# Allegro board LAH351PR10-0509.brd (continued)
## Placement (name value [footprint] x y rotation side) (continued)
CG887  0.47U_0201_4V_M  [C_0201]  33.32 62.21 90 bottom
CG888  4.7U_0402_4V_M  [C_0402]  34.09 62.21 90 bottom
CG889  0.47U_0201_4V_M  [C_0201]  35.31 62.21 90 bottom
CG895  20P_0402_50V8  [C_0402]  68.69 95.79 0 top
CG896  1U_0201_4V6M  [C_0201]  54.25 88.8 0 bottom
CG907  1U_0201_4V6M  [C_0201]  54.25 88.23 0 bottom
CG908  1U_0201_4V6M  [C_0201]  40.61 90.24 90 bottom
CG909  1U_0201_4V6M  [C_0201]  34.25 111.22 0 bottom
CG910  1U_0201_4V6M  [C_0201]  51.37 99.63 270 bottom
CG911  4.7U_0402_4V_M  [C_0402]  52.68 87.5 90 bottom
CG6501  22U_0603_4V_M  [C_0603]  53.91 87.34 0 bottom
CG6502  1U_0201_4V6M  [C_0201]  52.55 96.55 180 bottom
CG6506  4.7U_0402_4V_M  [C_0402]  56.52 113.36 90 bottom
CG6507  22U_0603_4V_M  [C_0603]  57.4 94.2 90 bottom
CG6508  1U_0201_4V6M  [C_0201]  58.55 113.53 90 bottom
CG6509  1U_0201_4V6M  [C_0201]  53.59 94.41 90 bottom
CG6522  0.47U_0201_4V_M  [C_0201]  39.05 127.94 90 bottom
CG6523  0.47U_0201_4V_M  [C_0201]  40.01 128.01 90 bottom
CG6524  0.47U_0201_4V_M  [C_0201]  36.6 128.93 0 bottom
CG6525  0.47U_0201_4V_M  [C_0201]  35.61 133.05 90 bottom
CG6526  0.47U_0201_4V_M  [C_0201]  35 136.98 0 bottom
CG6527  0.47U_0201_4V_M  [C_0201]  39.47 125.88 180 bottom
CG6528  0.47U_0201_4V_M  [C_0201]  42.51 134.99 270 top
CG6529  0.47U_0201_4V_M  [C_0201]  42.51 136.19 270 top
CG6530  0.47U_0201_4V_M  [C_0201]  42.51 137.4 270 top
CG6531  0.47U_0201_4V_M  [C_0201]  35.54 135.51 180 bottom
CG6532  0.47U_0201_4V_M  [C_0201]  38.6 137.26 90 bottom
CG6533  0.47U_0201_4V_M  [C_0201]  40.4 133.69 90 bottom
CG6534  0.47U_0201_4V_M  [C_0201]  38.73 136.03 180 bottom
CG6535  0.47U_0201_4V_M  [C_0201]  35.04 133.05 90 bottom
CG6536  0.47U_0201_4V_M  [C_0201]  30.23 127.83 270 bottom
CG6537  0.47U_0201_4V_M  [C_0201]  36.26 136.99 0 bottom
CG6538  0.47U_0201_4V_M  [C_0201]  32.09 128.3 0 bottom
CG6539  0.47U_0201_4V_M  [C_0201]  40.4 133.05 270 bottom
CG6540  0.47U_0201_4V_M  [C_0201]  40.01 126.48 90 bottom
CG6541  0.47U_0201_4V_M  [C_0201]  26.86 137.91 270 top
CG6542  0.47U_0201_4V_M  [C_0201]  35.53 136.18 180 bottom
CG6543  0.47U_0201_4V_M  [C_0201]  28.45 127.49 90 bottom
CG6544  0.47U_0201_4V_M  [C_0201]  33.6 126.77 90 bottom
CG6545  0.47U_0201_4V_M  [C_0201]  30.23 129.47 90 bottom
CG6546  0.47U_0201_4V_M  [C_0201]  37.45 137.14 270 bottom
CG6547  0.47U_0201_4V_M  [C_0201]  29.74 125.95 0 bottom
CG6548  0.47U_0201_4V_M  [C_0201]  37.34 134.88 270 bottom
CG6549  0.47U_0201_4V_M  [C_0201]  36.35 135.73 0 bottom
CG6550  0.47U_0201_4V_M  [C_0201]  29.02 127.49 90 bottom
CG6551  0.47U_0201_4V_M  [C_0201]  39.24 131.25 0 bottom
CG6552  0.47U_0201_4V_M  [C_0201]  39.05 133.66 90 bottom
CG6553  0.47U_0201_4V_M  [C_0201]  26.95 135.47 270 top
CG6554  0.47U_0201_4V_M  [C_0201]  37.05 130.58 0 bottom
CG6555  0.47U_0201_4V_M  [C_0201]  26.95 136.67 270 top
CG6556  0.47U_0201_4V_M  [C_0201]  37.65 127.58 90 bottom
CG6557  0.47U_0201_4V_M  [C_0201]  40.01 129.47 90 bottom
CG6558  0.47U_0201_4V_M  [C_0201]  51.4 128.81 0 bottom
CG6559  0.47U_0201_4V_M  [C_0201]  49.15 129.92 270 bottom
CG6560  0.47U_0201_4V_M  [C_0201]  50.8 127.24 90 bottom
CG6561  0.47U_0201_4V_M  [C_0201]  50.44 128.83 180 bottom
CG6562  0.47U_0201_4V_M  [C_0201]  51.25 138.66 270 bottom
CG6563  0.47U_0201_4V_M  [C_0201]  48.42 131.14 270 bottom
CG6564  0.47U_0201_4V_M  [C_0201]  47.14 139.79 0 bottom
CG6565  0.47U_0201_4V_M  [C_0201]  46.86 134.42 90 bottom
CG6566  0.47U_0201_4V_M  [C_0201]  47.84 129.24 0 bottom
CG6567  0.47U_0201_4V_M  [C_0201]  51.4 129.57 0 bottom
CG6568  0.47U_0201_4V_M  [C_0201]  46.93 127.94 90 bottom
CG6569  0.47U_0201_4V_M  [C_0201]  46.93 126.48 90 bottom
CG6570  0.47U_0201_4V_M  [C_0201]  54.42 134.94 270 bottom
CG6571  0.47U_0201_4V_M  [C_0201]  54.64 130.58 0 bottom
CG6572  0.47U_0201_4V_M  [C_0201]  54.71 128.3 180 bottom
CG6573  0.47U_0201_4V_M  [C_0201]  56.64 129.29 270 bottom
CG6574  0.47U_0201_4V_M  [C_0201]  54.71 128.93 180 bottom
CG6575  0.47U_0201_4V_M  [C_0201]  53.66 127 270 bottom
CG6576  0.47U_0201_4V_M  [C_0201]  56.71 131.19 270 bottom
CG6577  0.47U_0201_4V_M  [C_0201]  56.13 131.19 270 bottom
CG6578  0.47U_0201_4V_M  [C_0201]  55.05 134.94 270 bottom
CG6579  0.47U_0201_4V_M  [C_0201]  50.27 136.55 180 bottom
CG6580  0.47U_0201_4V_M  [C_0201]  49.66 134.88 270 bottom
CG6581  0.47U_0201_4V_M  [C_0201]  47.94 134.42 90 bottom
CG6582  0.47U_0201_4V_M  [C_0201]  54.19 136.55 0 bottom
CG6583  0.47U_0201_4V_M  [C_0201]  47.82 131.14 270 bottom
CG6584  0.47U_0201_4V_M  [C_0201]  54.78 137.12 180 bottom
CG6585  0.47U_0201_4V_M  [C_0201]  50.27 137.12 180 bottom
CG6586  0.47U_0201_4V_M  [C_0201]  59.63 138.72 270 top
CG6587  0.47U_0201_4V_M  [C_0201]  59.63 137.37 270 top
CG6588  0.47U_0201_4V_M  [C_0201]  59.63 135.48 90 top
CG6589  0.47U_0201_4V_M  [C_0201]  56.16 134.33 0 bottom
CG6590  0.47U_0201_4V_M  [C_0201]  57.99 130.51 270 bottom
CG6591  0.47U_0201_4V_M  [C_0201]  57.99 128.75 90 bottom
CG6592  0.47U_0201_4V_M  [C_0201]  57.99 127.54 90 bottom
CG6593  0.47U_0201_4V_M  [C_0201]  55.57 126.48 90 bottom
CG6594  0.47U_0201_4V_M  [C_0201]  13.08 113.91 90 bottom
CG6595  0.47U_0201_4V_M  [C_0201]  15.66 117.29 180 bottom
CG6596  0.47U_0201_4V_M  [C_0201]  4.83 109.46 90 bottom
CG6597  0.47U_0201_4V_M  [C_0201]  5.4 110.05 270 bottom
CG6598  0.47U_0201_4V_M  [C_0201]  3.86 113.19 0 bottom
CG6599  0.47U_0201_4V_M  [C_0201]  3.38 109.65 0 bottom
CG6600  0.47U_0201_4V_M  [C_0201]  8.04 106.58 180 bottom
CG6601  0.47U_0201_4V_M  [C_0201]  5.4 113.97 90 bottom
CG6602  0.47U_0201_4V_M  [C_0201]  7.07 114.65 0 bottom
CG6603  0.47U_0201_4V_M  [C_0201]  14.07 106.58 180 bottom
CG6604  0.47U_0201_4V_M  [C_0201]  14.83 110.52 180 bottom
CG6605  0.47U_0201_4V_M  [C_0201]  5.8 117.31 0 bottom
CG6606  0.47U_0201_4V_M  [C_0201]  10.49 117.26 0 bottom
CG6607  0.47U_0201_4V_M  [C_0201]  4.38 106.62 0 bottom
CG6608  0.47U_0201_4V_M  [C_0201]  14.17 117.29 180 bottom
CG6609  0.47U_0201_4V_M  [C_0201]  13.72 114.49 270 bottom
CG6610  0.47U_0201_4V_M  [C_0201]  2.8 106.63 0 bottom
CG6611  0.47U_0201_4V_M  [C_0201]  8.13 108.26 90 bottom
CG6612  0.47U_0201_4V_M  [C_0201]  12.55 106.58 180 bottom
CG6613  0.47U_0201_4V_M  [C_0201]  3.39 114.26 0 bottom
CG6614  0.47U_0201_4V_M  [C_0201]  9.65 115.52 270 bottom
CG6615  0.47U_0201_4V_M  [C_0201]  3.58 121.58 0 top
CG6616  0.47U_0201_4V_M  [C_0201]  2.33 121.58 0 top
CG6617  0.47U_0201_4V_M  [C_0201]  2.95 117.31 0 bottom
CG6618  0.47U_0201_4V_M  [C_0201]  12.19 110.05 270 bottom
CG6619  0.47U_0201_4V_M  [C_0201]  9.06 115.52 270 bottom
CG6620  0.47U_0201_4V_M  [C_0201]  4.47 117.31 0 bottom
CG6621  0.47U_0201_4V_M  [C_0201]  12.68 117.29 180 bottom
CG6622  0.47U_0201_4V_M  [C_0201]  8.04 117.31 180 bottom
CG6623  0.47U_0201_4V_M  [C_0201]  8.76 108.26 90 bottom
CG6624  0.47U_0201_4V_M  [C_0201]  7.05 109.54 270 bottom
CG6625  0.47U_0201_4V_M  [C_0201]  15.6 106.58 180 bottom
CG6626  0.47U_0201_4V_M  [C_0201]  10.5 106.58 0 bottom
CG6627  0.47U_0201_4V_M  [C_0201]  13.72 109.34 90 bottom
CG6628  0.47U_0201_4V_M  [C_0201]  2.33 104.59 0 top
CG6629  0.47U_0201_4V_M  [C_0201]  3.53 104.58 0 top
CG6630  0.47U_0201_4V_M  [C_0201]  7.07 126.39 0 bottom
CG6631  0.47U_0201_4V_M  [C_0201]  6.31 127.31 0 bottom
CG6632  0.47U_0201_4V_M  [C_0201]  3.94 126.43 270 bottom
CG6633  0.47U_0201_4V_M  [C_0201]  7.98 123.66 180 bottom
CG6634  0.47U_0201_4V_M  [C_0201]  5.03 136.41 0 top
CG6635  0.47U_0201_4V_M  [C_0201]  3.51 136.41 0 top
CG6636  0.47U_0201_4V_M  [C_0201]  4.78 121.58 0 top
CG6637  0.47U_0201_4V_M  [C_0201]  8.26 132.72 270 bottom
CG6638  0.47U_0201_4V_M  [C_0201]  13.08 130.99 90 bottom
CG6639  0.47U_0201_4V_M  [C_0201]  3.94 131.75 90 bottom
CG6640  0.47U_0201_4V_M  [C_0201]  7.08 130.81 0 bottom
CG6641  0.47U_0201_4V_M  [C_0201]  14.83 126.71 180 bottom
CG6642  0.47U_0201_4V_M  [C_0201]  3.71 127.66 0 bottom
CG6643  0.47U_0201_4V_M  [C_0201]  3.07 123.66 0 bottom
CG6644  0.47U_0201_4V_M  [C_0201]  10.88 125.19 0 bottom
CG6645  0.47U_0201_4V_M  [C_0201]  16.07 124.2 90 bottom
CG6646  0.47U_0201_4V_M  [C_0201]  14.25 124.61 0 bottom
CG6647  0.47U_0201_4V_M  [C_0201]  6.09 121.58 0 top
CG6648  0.47U_0201_4V_M  [C_0201]  7.07 131.98 0 bottom
CG6649  0.47U_0201_4V_M  [C_0201]  10.76 133.5 0 bottom
CG6650  0.47U_0201_4V_M  [C_0201]  13.72 131.57 270 bottom
CG6651  0.47U_0201_4V_M  [C_0201]  6.29 130.74 90 bottom
CG6652  0.47U_0201_4V_M  [C_0201]  14.83 127.6 180 bottom
CG6653  0.47U_0201_4V_M  [C_0201]  12.19 127.07 270 bottom
CG6654  0.47U_0201_4V_M  [C_0201]  4.41 123.66 0 bottom
CG6655  0.47U_0201_4V_M  [C_0201]  5.99 123.66 0 bottom
CG6656  0.47U_0201_4V_M  [C_0201]  7.72 125.19 180 bottom
CG6657  0.47U_0201_4V_M  [C_0201]  12.73 124.61 0 bottom
CG6658  0.47U_0201_4V_M  [C_0201]  10.5 123.73 0 bottom
CG6659  0.47U_0201_4V_M  [C_0201]  5.4 130.99 90 bottom
CG6660  0.47U_0201_4V_M  [C_0201]  7.07 131.41 0 bottom
CG6661  0.47U_0201_4V_M  [C_0201]  8.84 132.73 270 bottom
CG6662  0.47U_0201_4V_M  [C_0201]  12.73 133.5 0 bottom
CG6663  0.47U_0201_4V_M  [C_0201]  14.12 133.5 0 bottom
CG6664  0.47U_0201_4V_M  [C_0201]  16.07 133.8 270 bottom
CG6665  0.47U_0201_4V_M  [C_0201]  3.64 130.46 0 bottom
CG6666  0.47U_0201_4V_M  [C_0201]  12.56 72.45 180 bottom
CG6667  0.47U_0201_4V_M  [C_0201]  10.76 82.26 0 bottom
CG6668  0.47U_0201_4V_M  [C_0201]  11.06 80.15 90 bottom
CG6669  0.47U_0201_4V_M  [C_0201]  4.83 75.24 90 bottom
CG6670  0.47U_0201_4V_M  [C_0201]  7.05 75.38 270 bottom
CG6671  0.47U_0201_4V_M  [C_0201]  14.77 79.09 180 bottom
CG6672  0.47U_0201_4V_M  [C_0201]  4.38 73.4 90 bottom
CG6673  0.47U_0201_4V_M  [C_0201]  8.1 72.35 180 bottom
CG6674  0.47U_0201_4V_M  [C_0201]  10.22 74.16 90 bottom
CG6675  0.47U_0201_4V_M  [C_0201]  5.4 75.82 270 bottom
CG6676  0.47U_0201_4V_M  [C_0201]  10.49 81.42 270 bottom
CG6677  0.47U_0201_4V_M  [C_0201]  10.49 72.45 0 bottom
CG6678  0.47U_0201_4V_M  [C_0201]  9.02 74.09 90 bottom
CG6679  0.47U_0201_4V_M  [C_0201]  11.93 85.18 0 top
CG6680  0.47U_0201_4V_M  [C_0201]  3.68 73.4 90 bottom
CG6681  0.47U_0201_4V_M  [C_0201]  8 74.16 90 bottom
CG6682  0.47U_0201_4V_M  [C_0201]  13.65 80.33 270 bottom
CG6683  0.47U_0201_4V_M  [C_0201]  6.29 76.14 270 bottom
CG6684  0.47U_0201_4V_M  [C_0201]  4.47 83.15 0 bottom
CG6685  0.47U_0201_4V_M  [C_0201]  14.57 75.15 0 bottom
CG6686  0.47U_0201_4V_M  [C_0201]  11.53 74.83 180 bottom
CG6687  0.47U_0201_4V_M  [C_0201]  5.93 79.15 0 bottom
CG6688  0.47U_0201_4V_M  [C_0201]  15.47 72.42 180 bottom
CG6689  0.47U_0201_4V_M  [C_0201]  3.85 80.1 180 bottom
CG6690  0.47U_0201_4V_M  [C_0201]  7.59 73.37 180 bottom
CG6691  0.47U_0201_4V_M  [C_0201]  14.16 72.43 180 bottom
CG6692  0.47U_0201_4V_M  [C_0201]  9.78 81.41 270 bottom
CG6693  0.47U_0201_4V_M  [C_0201]  12.19 79.43 90 bottom
CG6694  0.47U_0201_4V_M  [C_0201]  13.26 85.18 0 top
CG6695  0.47U_0201_4V_M  [C_0201]  2.95 83.15 0 bottom
CG6696  0.47U_0201_4V_M  [C_0201]  7.66 82.2 180 bottom
CG6697  0.47U_0201_4V_M  [C_0201]  16.13 73.01 90 bottom
CG6698  0.47U_0201_4V_M  [C_0201]  8.13 81.47 270 bottom
CG6699  0.47U_0201_4V_M  [C_0201]  12.61 73.37 180 bottom
CG6700  0.47U_0201_4V_M  [C_0201]  7.05 80.19 90 bottom
CG6701  0.47U_0201_4V_M  [C_0201]  14.79 85.18 0 top
CG6702  0.47U_0201_4V_M  [C_0201]  13.08 92.97 270 bottom
CG6703  0.47U_0201_4V_M  [C_0201]  2.95 89.56 0 bottom
CG6704  0.47U_0201_4V_M  [C_0201]  10.5 89.5 0 bottom
CG6705  0.47U_0201_4V_M  [C_0201]  5.46 92.87 270 bottom
CG6706  0.47U_0201_4V_M  [C_0201]  12.32 100.19 180 bottom
CG6707  0.47U_0201_4V_M  [C_0201]  4.53 89.56 0 bottom
CG6708  0.47U_0201_4V_M  [C_0201]  3.96 92.2 270 bottom
CG6709  0.47U_0201_4V_M  [C_0201]  14.86 97.21 90 bottom
CG6710  0.47U_0201_4V_M  [C_0201]  12.49 89.52 180 bottom
CG6711  0.47U_0201_4V_M  [C_0201]  13.65 97.14 90 bottom
CG6712  0.47U_0201_4V_M  [C_0201]  14.11 89.52 180 bottom
CG6713  0.47U_0201_4V_M  [C_0201]  13.08 97.14 90 bottom
CG6714  0.47U_0201_4V_M  [C_0201]  5.4 96.89 90 bottom
CG6715  0.47U_0201_4V_M  [C_0201]  15.54 89.52 180 bottom
CG6716  0.47U_0201_4V_M  [C_0201]  4.83 97.48 270 bottom
CG6717  0.47U_0201_4V_M  [C_0201]  11.41 92.59 180 bottom
CG6718  0.47U_0201_4V_M  [C_0201]  10.82 91.09 0 bottom
CG6719  0.47U_0201_4V_M  [C_0201]  10.55 100.19 0 bottom
CG6720  0.47U_0201_4V_M  [C_0201]  9.91 98.36 270 bottom
CG6721  0.47U_0201_4V_M  [C_0201]  8.98 90.26 0 bottom
CG6722  0.47U_0201_4V_M  [C_0201]  14.77 93.44 180 bottom
CG6723  0.47U_0201_4V_M  [C_0201]  5.99 89.56 0 bottom
CG6724  0.47U_0201_4V_M  [C_0201]  3.71 93.5 0 bottom
CG6725  0.47U_0201_4V_M  [C_0201]  2.88 100.23 0 bottom
CG6726  0.47U_0201_4V_M  [C_0201]  55.82 64.39 270 bottom
CG6727  0.47U_0201_4V_M  [C_0201]  56.39 70.41 90 bottom
CG6728  0.47U_0201_4V_M  [C_0201]  54.23 70.67 90 bottom
CG6729  0.47U_0201_4V_M  [C_0201]  45.15 67.95 270 bottom
CG6730  0.47U_0201_4V_M  [C_0201]  45.09 65.73 270 bottom
CG6731  0.47U_0201_4V_M  [C_0201]  45.07 72.56 90 bottom
CG6732  0.47U_0201_4V_M  [C_0201]  55.22 62.32 180 bottom
CG6733  0.47U_0201_4V_M  [C_0201]  47.73 74.42 180 bottom
CG6734  0.47U_0201_4V_M  [C_0201]  48.58 72.52 0 bottom
CG6735  0.47U_0201_4V_M  [C_0201]  45.06 74.08 90 bottom
CG6736  0.47U_0201_4V_M  [C_0201]  53.09 63.82 270 bottom
CG6737  0.47U_0201_4V_M  [C_0201]  53.02 71.31 270 bottom
CG6738  0.47U_0201_4V_M  [C_0201]  55.82 62.6 90 bottom
CG6739  0.47U_0201_4V_M  [C_0201]  55.82 73.85 270 bottom
CG6740  0.47U_0201_4V_M  [C_0201]  54.23 67.69 270 bottom
CG6741  0.47U_0201_4V_M  [C_0201]  51.82 63.68 90 bottom
CG6742  0.47U_0201_4V_M  [C_0201]  45.09 64.2 270 bottom
CG6743  0.47U_0201_4V_M  [C_0201]  53.31 73.56 180 bottom
CG6744  0.47U_0201_4V_M  [C_0201]  47.84 64.8 0 bottom
CG6745  0.47U_0201_4V_M  [C_0201]  49.09 74.68 270 bottom
CG6746  0.47U_0201_4V_M  [C_0201]  48.58 65.78 0 bottom
CG6747  0.47U_0201_4V_M  [C_0201]  51.82 74.74 270 bottom
CG6748  0.47U_0201_4V_M  [C_0201]  53.02 66.98 90 bottom
CG6749  0.47U_0201_4V_M  [C_0201]  52.73 72.99 0 bottom
CG6750  0.47U_0201_4V_M  [C_0201]  45.09 70.35 90 bottom
CG6751  0.47U_0201_4V_M  [C_0201]  55.82 72.65 270 bottom
CG6752  0.47U_0201_4V_M  [C_0201]  55.82 70.41 90 bottom
CG6753  0.47U_0201_4V_M  [C_0201]  49.09 63.49 90 bottom
CG6754  0.47U_0201_4V_M  [C_0201]  55.82 65.84 90 bottom
CG6755  0.47U_0201_4V_M  [C_0201]  46 67.53 0 bottom
CG6756  0.47U_0201_4V_M  [C_0201]  46.29 70.79 90 bottom
CG6757  0.47U_0201_4V_M  [C_0201]  48.26 71.38 270 bottom
CG6758  0.47U_0201_4V_M  [C_0201]  45.55 62.26 0 bottom
CG6759  0.47U_0201_4V_M  [C_0201]  52.32 66.35 90 bottom
CG6760  0.47U_0201_4V_M  [C_0201]  48.45 66.54 90 bottom
CG6761  0.47U_0201_4V_M  [C_0201]  46.76 70.13 0 bottom
CG6762  0.47U_0201_4V_M  [C_0201]  38.65 75.02 180 bottom
CG6763  0.47U_0201_4V_M  [C_0201]  38.04 68.33 180 bottom
CG6764  0.47U_0201_4V_M  [C_0201]  37.95 70.2 180 bottom
CG6765  0.47U_0201_4V_M  [C_0201]  31.69 66.98 90 bottom
CG6766  0.47U_0201_4V_M  [C_0201]  39.72 64.39 90 bottom
CG6767  0.47U_0201_4V_M  [C_0201]  39.69 62.85 90 bottom
CG6768  0.47U_0201_4V_M  [C_0201]  35.31 63.43 90 bottom
CG6769  0.47U_0201_4V_M  [C_0201]  36.83 66.98 90 bottom
CG6770  0.47U_0201_4V_M  [C_0201]  28.96 75.5 270 bottom
CG6771  0.47U_0201_4V_M  [C_0201]  28.96 72.39 270 bottom
CG6772  0.47U_0201_4V_M  [C_0201]  28.96 70.41 90 bottom
CG6773  0.47U_0201_4V_M  [C_0201]  30.04 73.92 270 bottom
CG6774  0.47U_0201_4V_M  [C_0201]  28.96 65.9 90 bottom
CG6775  0.47U_0201_4V_M  [C_0201]  35.75 65.73 270 bottom
CG6776  0.47U_0201_4V_M  [C_0201]  35.75 74.74 270 bottom
CG6777  0.47U_0201_4V_M  [C_0201]  38.04 67.71 180 bottom
CG6778  0.47U_0201_4V_M  [C_0201]  39.72 67.96 270 bottom
CG6779  0.47U_0201_4V_M  [C_0201]  32.89 74.55 270 bottom
CG6780  0.47U_0201_4V_M  [C_0201]  39.67 72.8 90 bottom
CG6781  0.47U_0201_4V_M  [C_0201]  39.71 65.98 90 bottom
CG6782  0.47U_0201_4V_M  [C_0201]  35.43 67.24 90 bottom
CG6783  0.47U_0201_4V_M  [C_0201]  30 72.61 0 bottom
CG6784  0.47U_0201_4V_M  [C_0201]  28.96 73.85 270 bottom
CG6785  0.47U_0201_4V_M  [C_0201]  29.93 64.48 0 bottom
CG6786  0.47U_0201_4V_M  [C_0201]  29.02 62.85 90 bottom
CG6787  0.47U_0201_4V_M  [C_0201]  29.02 64.38 90 bottom
CG6788  0.47U_0201_4V_M  [C_0201]  28.96 68.01 270 bottom
CG6789  0.47U_0201_4V_M  [C_0201]  39.69 72.14 270 bottom
CG6790  0.47U_0201_4V_M  [C_0201]  30.61 68.27 270 bottom
CG6791  0.47U_0201_4V_M  [C_0201]  30.82 69.43 0 bottom
CG6792  0.47U_0201_4V_M  [C_0201]  36.28 73.05 0 bottom
CG6793  0.47U_0201_4V_M  [C_0201]  31.94 63.76 270 bottom
CG6794  0.47U_0201_4V_M  [C_0201]  39.68 74.21 90 bottom
CG6795  0.47U_0201_4V_M  [C_0201]  39.62 70.35 90 bottom
CG6796  0.47U_0201_4V_M  [C_0201]  31.92 71.34 180 bottom
CG6797  0.47U_0201_4V_M  [C_0201]  32.96 63.55 90 bottom
CG6802  1U_0402_25V6K  [C_0402]  9.59 39.4 90 top
CG6803  0.47U_0201_4V_M  [C_0201]  2.49 127.39 0 bottom
CG6804  4.7U_0402_4V_M  [C_0402]  56.32 94.5 90 bottom
CG6815  1U_0201_4V6M  [C_0201]  25.97 139.65 180 bottom
CG6816  1U_0201_4V6M  [C_0201]  51.17 90.15 90 bottom
CG6817  1U_0201_4V6M  [C_0201]  16.19 79.87 90 bottom
CG6818  4.7U_0402_4V_M  [C_0402]  51.88 89.3 0 bottom
CG6819  1U_0402_6.3V6K  [C_0402]  2.83 110.8 0 bottom
CG6820  1U_0402_6.3V6K  [C_0402]  2.53 128.42 0 bottom
CG6821  1U_0402_6.3V6K  [C_0402]  2.45 74.73 0 bottom
CG6822  4.7U_0402_4V_M  [C_0402]  26.2 140.41 180 bottom
CG6823  4.7U_0402_4V_M  [C_0402]  2.35 91.58 0 bottom
CG6824  0.1U_0201_6.3V6K  [C_0201]  2.46 96.26 0 bottom
CG6825  18P_0402_50V8J  [C_0402]  70.8 83.64 90 top
CG6826  3.9P_0402_50V+-0.25PF  [C_0402]  25.15 122.19 90 top
CG6828  1U_0201_4V6M  [C_0201]  41.18 111.92 270 bottom
CG6829  1U_0201_4V6M  [C_0201]  42.32 90.29 90 bottom
CG6830  1U_0201_4V6M  [C_0201]  30.63 90.23 90 bottom
CG6831  1U_0201_4V6M  [C_0201]  30.05 90.23 90 bottom
CG6832  1U_0201_4V6M  [C_0201]  31.72 111.8 270 bottom
CG6833  1U_0201_4V6M  [C_0201]  36.61 111.8 270 bottom
CG6834  1U_0201_4V6M  [C_0201]  41.75 111.92 270 bottom
CG6835  1U_0201_4V6M  [C_0201]  38.41 111.73 270 bottom
CG6836  1U_0201_4V6M  [C_0201]  44.73 111.92 270 bottom
CG6837  1U_0201_4V6M  [C_0201]  30.45 111.8 270 bottom
CG6838  1U_0201_4V6M  [C_0201]  30.63 106.52 0 bottom
CG6839  1U_0201_4V6M  [C_0201]  30.63 110.33 0 bottom
CG6840  1U_0201_4V6M  [C_0201]  30.63 109.69 0 bottom
CG6841  1U_0201_4V6M  [C_0201]  30.63 102.71 0 bottom
CG6842  1U_0201_4V6M  [C_0201]  29.46 94.93 0 bottom
CG6843  1U_0201_4V6M  [C_0201]  37.24 90.26 90 bottom
CG6844  1U_0201_4V6M  [C_0201]  36.67 90.26 90 bottom
CG6845  1U_0201_4V6M  [C_0201]  31.77 90.23 90 bottom
CG6846  1U_0201_4V6M  [C_0201]  31.2 90.23 90 bottom
CG6847  1U_0201_4V6M  [C_0201]  29.46 91.44 0 bottom
CG6848  1U_0201_4V6M  [C_0201]  29.46 93.6 0 bottom
CG6849  1U_0201_4V6M  [C_0201]  29.46 95.5 0 bottom
CG6850  1U_0201_4V6M  [C_0201]  29.46 97.34 0 bottom
CG6851  1U_0201_4V6M  [C_0201]  30.63 102.07 0 bottom
CG6852  0.47U_0201_4V_M  [C_0201]  30.63 108.42 0 bottom
CG6853  0.47U_0201_4V_M  [C_0201]  30.63 104.61 0 bottom
CG6854  0.47U_0201_4V_M  [C_0201]  30.63 105.25 0 bottom
CG6855  0.47U_0201_4V_M  [C_0201]  30.63 105.88 0 bottom
CG6856  0.47U_0201_4V_M  [C_0201]  30.63 107.15 0 bottom
CG6857  0.47U_0201_4V_M  [C_0201]  30.63 107.79 0 bottom
CG6858  0.47U_0201_4V_M  [C_0201]  31.15 111.8 270 bottom
CG6859  0.47U_0201_4V_M  [C_0201]  32.29 111.8 270 bottom
CG6860  0.47U_0201_4V_M  [C_0201]  35.46 111.8 270 bottom
CG6861  0.47U_0201_4V_M  [C_0201]  36.04 111.8 270 bottom
CG6862  0.47U_0201_4V_M  [C_0201]  42.32 111.92 270 bottom
CG6863  0.47U_0201_4V_M  [C_0201]  42.89 111.92 270 bottom
CG6864  0.47U_0201_4V_M  [C_0201]  41.18 90.26 90 bottom
CG6865  0.47U_0201_4V_M  [C_0201]  42.89 90.29 90 bottom
CG6866  0.47U_0201_4V_M  [C_0201]  41.75 90.26 90 bottom
CG6867  0.47U_0201_4V_M  [C_0201]  38.96 90.26 90 bottom
CG6868  0.47U_0201_4V_M  [C_0201]  38.38 90.26 90 bottom
CG6869  0.47U_0201_4V_M  [C_0201]  37.81 90.26 90 bottom
CG6870  0.47U_0201_4V_M  [C_0201]  36.1 90.26 90 bottom
CG6871  0.47U_0201_4V_M  [C_0201]  32.34 90.23 90 bottom
CG6872  0.47U_0201_4V_M  [C_0201]  29.46 92.07 0 bottom
CG6873  0.47U_0201_4V_M  [C_0201]  29.46 92.96 0 bottom
CG6874  0.47U_0201_4V_M  [C_0201]  29.46 96.14 0 bottom
CG6875  0.47U_0201_4V_M  [C_0201]  29.46 96.77 0 bottom
CG6876  10U_0603_4V_M  [C_0603]  33.24 89.4 90 bottom
CG6877  10U_0603_4V_M  [C_0603]  43.81 111.91 270 bottom
CG6878  10U_0603_4V_M  [C_0603]  39.3 111.7 270 bottom
CG6879  10U_0603_4V_M  [C_0603]  29.57 99.55 0 bottom
CG6880  10U_0603_4V_M  [C_0603]  29.57 98.28 0 bottom
CG6881  10U_0603_4V_M  [C_0603]  25.3 103.56 0 bottom
CG6882  10U_0603_4V_M  [C_0603]  25.3 105.34 0 bottom
CG6883  10U_0603_4V_M  [C_0603]  34.83 116.2 270 bottom
CG6884  10U_0603_4V_M  [C_0603]  25.3 96.19 0 bottom
CG6885  10U_0603_4V_M  [C_0603]  25.3 97.97 0 bottom
CG6886  10U_0603_4V_M  [C_0603]  25.3 99.88 0 bottom
CG6887  10U_0603_4V_M  [C_0603]  25.3 101.78 0 bottom
CG6888  22U_0603_4V_M  [C_0603]  25.3 107.12 0 bottom
CG6889  22U_0603_4V_M  [C_0603]  25.3 108.89 0 bottom
CG6890  22U_0603_4V_M  [C_0603]  32.1 116.2 270 bottom
CG6891  22U_0603_4V_M  [C_0603]  50.07 116.2 270 bottom
CG6892  22U_0603_4V_M  [C_0603]  47.66 116.2 270 bottom
CG6893  22U_0603_4V_M  [C_0603]  44.99 116.2 270 bottom
CG6894  22U_0603_4V_M  [C_0603]  42.32 116.2 270 bottom
CG6895  22U_0603_4V_M  [C_0603]  40.04 116.2 270 bottom
CG6896  22U_0603_4V_M  [C_0603]  37.62 116.2 270 bottom
CG6897  1U_0201_4V6M  [C_0201]  32.22 109.06 0 bottom
CG6898  1U_0201_4V6M  [C_0201]  33.62 109.06 0 bottom
CG6899  1U_0201_4V6M  [C_0201]  34.95 109.06 0 bottom
CG6900  1U_0201_4V6M  [C_0201]  36.35 109.06 0 bottom
CG6901  1U_0201_4V6M  [C_0201]  37.74 109.06 0 bottom
CG6902  1U_0201_4V6M  [C_0201]  39.14 109.06 0 bottom
CG6903  1U_0201_4V6M  [C_0201]  40.47 109.06 0 bottom
CG6904  1U_0201_4V6M  [C_0201]  41.74 109.06 0 bottom
CG6905  1U_0201_4V6M  [C_0201]  43.14 109.06 0 bottom
CG6906  1U_0201_4V6M  [C_0201]  44.48 109.06 0 bottom
CG6907  1U_0201_4V6M  [C_0201]  47.21 109.69 0 bottom
CG6908  1U_0201_4V6M  [C_0201]  37.74 101.44 0 bottom
CG6909  1U_0201_4V6M  [C_0201]  39.14 101.44 0 bottom
CG6910  1U_0201_4V6M  [C_0201]  37.74 107.79 0 bottom
CG6911  1U_0201_4V6M  [C_0201]  39.14 107.79 0 bottom
CG6912  1U_0201_4V6M  [C_0201]  40.47 107.79 0 bottom
CG6913  1U_0201_4V6M  [C_0201]  41.74 107.79 0 bottom
CG6914  1U_0201_4V6M  [C_0201]  43.14 107.79 0 bottom
CG6915  1U_0201_4V6M  [C_0201]  44.48 107.79 0 bottom
CG6916  1U_0201_4V6M  [C_0201]  37.74 110.33 0 bottom
CG6917  1U_0201_4V6M  [C_0201]  32.22 110.33 0 bottom
CG6918  1U_0201_4V6M  [C_0201]  48.54 109.69 0 bottom
CG6919  1U_0201_4V6M  [C_0201]  37.74 102.07 0 bottom
CG6920  1U_0201_4V6M  [C_0201]  39.14 102.07 0 bottom
CG6921  1U_0201_4V6M  [C_0201]  32.22 107.79 0 bottom
CG6922  1U_0201_4V6M  [C_0201]  33.62 107.79 0 bottom
CG6923  1U_0201_4V6M  [C_0201]  34.95 107.79 0 bottom
CG6924  1U_0201_4V6M  [C_0201]  36.35 107.79 0 bottom
CG6925  1U_0201_4V6M  [C_0201]  40.47 102.07 0 bottom
CG6926  1U_0201_4V6M  [C_0201]  36.35 110.33 0 bottom
CG6927  1U_0201_4V6M  [C_0201]  40.47 101.44 0 bottom
CG6928  1U_0201_4V6M  [C_0201]  41.74 101.44 0 bottom
CG6929  1U_0201_4V6M  [C_0201]  34.95 110.33 0 bottom
CG6930  1U_0201_4V6M  [C_0201]  47.21 108.42 0 bottom
CG6931  1U_0201_4V6M  [C_0201]  48.54 108.42 0 bottom
CG6932  1U_0201_4V6M  [C_0201]  44.48 101.44 0 bottom
CG6933  1U_0201_4V6M  [C_0201]  49.94 108.42 0 bottom
CG6934  1U_0201_4V6M  [C_0201]  33.62 110.33 0 bottom
CG6935  1U_0201_4V6M  [C_0201]  43.14 101.44 0 bottom
CG6936  1U_0201_4V6M  [C_0201]  49.94 109.69 0 bottom
CG6937  1U_0201_4V6M  [C_0201]  32.22 109.69 0 bottom
CG6938  1U_0201_4V6M  [C_0201]  33.62 109.69 0 bottom
CG6939  1U_0201_4V6M  [C_0201]  34.95 109.69 0 bottom
CG6940  1U_0201_4V6M  [C_0201]  36.35 109.69 0 bottom
CG6941  1U_0201_4V6M  [C_0201]  37.74 109.69 0 bottom
CG6942  1U_0201_4V6M  [C_0201]  44.48 109.69 0 bottom
CG6943  1U_0201_4V6M  [C_0201]  40.47 109.69 0 bottom
CG6944  1U_0201_4V6M  [C_0201]  41.74 109.69 0 bottom
CG6945  1U_0201_4V6M  [C_0201]  45.87 109.69 0 bottom
CG6946  1U_0201_4V6M  [C_0201]  32.22 106.52 0 bottom
CG6947  1U_0201_4V6M  [C_0201]  33.62 106.52 0 bottom
CG6948  1U_0201_4V6M  [C_0201]  34.95 106.52 0 bottom
CG6949  1U_0201_4V6M  [C_0201]  36.35 106.52 0 bottom
CG6950  1U_0201_4V6M  [C_0201]  37.74 106.52 0 bottom
CG6951  1U_0201_4V6M  [C_0201]  39.14 106.52 0 bottom
CG6952  1U_0201_4V6M  [C_0201]  40.47 106.52 0 bottom
CG6953  1U_0201_4V6M  [C_0201]  41.74 106.52 0 bottom
CG6954  1U_0201_4V6M  [C_0201]  43.14 106.52 0 bottom
CG6955  1U_0201_4V6M  [C_0201]  44.48 106.52 0 bottom
CG6956  1U_0201_4V6M  [C_0201]  45.87 106.52 0 bottom
CG6957  1U_0201_4V6M  [C_0201]  47.21 106.52 0 bottom
CG6958  1U_0201_4V6M  [C_0201]  48.54 106.52 0 bottom
CG6959  1U_0201_4V6M  [C_0201]  49.94 106.52 0 bottom
CG6960  1U_0201_4V6M  [C_0201]  32.22 105.25 0 bottom
CG6961  1U_0201_4V6M  [C_0201]  33.62 105.25 0 bottom
CG6962  1U_0201_4V6M  [C_0201]  34.95 105.25 0 bottom
CG6963  1U_0201_4V6M  [C_0201]  36.35 105.25 0 bottom
CG6964  1U_0201_4V6M  [C_0201]  37.74 105.25 0 bottom
CG6965  1U_0201_4V6M  [C_0201]  39.14 105.25 0 bottom
CG6966  1U_0201_4V6M  [C_0201]  40.47 105.25 0 bottom
CG6967  1U_0201_4V6M  [C_0201]  41.74 105.25 0 bottom
CG6968  1U_0201_4V6M  [C_0201]  43.14 105.25 0 bottom
CG6969  1U_0201_4V6M  [C_0201]  44.48 105.25 0 bottom
CG6970  1U_0201_4V6M  [C_0201]  45.87 105.25 0 bottom
CG6971  1U_0201_4V6M  [C_0201]  47.21 105.25 0 bottom
CG6972  1U_0201_4V6M  [C_0201]  48.54 105.25 0 bottom
CG6973  1U_0201_4V6M  [C_0201]  49.94 105.25 0 bottom
CG6974  1U_0201_4V6M  [C_0201]  45.87 107.79 0 bottom
CG6975  1U_0201_4V6M  [C_0201]  47.21 107.79 0 bottom
CG6976  1U_0201_4V6M  [C_0201]  48.54 107.79 0 bottom
CG6977  1U_0201_4V6M  [C_0201]  49.94 107.79 0 bottom
CG6978  1U_0201_4V6M  [C_0201]  32.22 104.61 0 bottom
CG6979  1U_0201_4V6M  [C_0201]  33.62 104.61 0 bottom
CG6980  1U_0201_4V6M  [C_0201]  34.95 104.61 0 bottom
CG6981  1U_0201_4V6M  [C_0201]  36.35 104.61 0 bottom
CG6982  1U_0201_4V6M  [C_0201]  37.74 104.61 0 bottom
CG6983  1U_0201_4V6M  [C_0201]  39.14 104.61 0 bottom
CG6984  1U_0201_4V6M  [C_0201]  40.47 104.61 0 bottom
CG6985  1U_0201_4V6M  [C_0201]  41.74 104.61 0 bottom
CG6986  1U_0201_4V6M  [C_0201]  43.14 104.61 0 bottom
CG6987  1U_0201_4V6M  [C_0201]  44.48 104.61 0 bottom
CG6988  1U_0201_4V6M  [C_0201]  45.87 104.61 0 bottom
CG6989  1U_0201_4V6M  [C_0201]  47.21 104.61 0 bottom
CG6990  0.47U_0201_4V_M  [C_0201]  32.22 108.42 0 bottom
CG6991  0.47U_0201_4V_M  [C_0201]  33.62 108.42 0 bottom
CG6992  0.47U_0201_4V_M  [C_0201]  34.95 108.42 0 bottom
CG6993  0.47U_0201_4V_M  [C_0201]  36.35 108.42 0 bottom
CG6994  0.47U_0201_4V_M  [C_0201]  37.74 108.42 0 bottom
CG6995  0.47U_0201_4V_M  [C_0201]  39.14 108.42 0 bottom
CG6996  0.47U_0201_4V_M  [C_0201]  40.47 108.42 0 bottom
CG6997  0.47U_0201_4V_M  [C_0201]  41.74 108.42 0 bottom
CG6998  0.47U_0201_4V_M  [C_0201]  43.14 108.42 0 bottom
CG6999  0.47U_0201_4V_M  [C_0201]  44.48 108.42 0 bottom
CG7000  1U_0201_4V6M  [C_0201]  48.54 104.61 0 bottom
CG7001  1U_0201_4V6M  [C_0201]  49.94 104.61 0 bottom
CG7002  0.47U_0201_4V_M  [C_0201]  45.87 108.42 0 bottom
CG7003  0.47U_0201_4V_M  [C_0201]  32.22 107.15 0 bottom
CG7004  0.47U_0201_4V_M  [C_0201]  33.62 107.15 0 bottom
CG7005  0.47U_0201_4V_M  [C_0201]  34.95 107.15 0 bottom
CG7006  0.47U_0201_4V_M  [C_0201]  36.35 107.15 0 bottom
CG7007  0.47U_0201_4V_M  [C_0201]  37.74 107.15 0 bottom
CG7008  0.47U_0201_4V_M  [C_0201]  39.14 107.15 0 bottom
CG7009  0.47U_0201_4V_M  [C_0201]  40.47 107.15 0 bottom
CG7010  0.47U_0201_4V_M  [C_0201]  41.74 107.15 0 bottom
CG7011  0.47U_0201_4V_M  [C_0201]  43.14 107.15 0 bottom
CG7012  0.47U_0201_4V_M  [C_0201]  44.48 107.15 0 bottom
CG7013  0.47U_0201_4V_M  [C_0201]  45.87 107.15 0 bottom
CG7014  0.47U_0201_4V_M  [C_0201]  47.21 107.15 0 bottom
CG7015  0.47U_0201_4V_M  [C_0201]  48.54 107.15 0 bottom
CG7016  0.47U_0201_4V_M  [C_0201]  49.94 107.15 0 bottom
CG7017  0.47U_0201_4V_M  [C_0201]  32.22 105.88 0 bottom
CG7018  0.47U_0201_4V_M  [C_0201]  33.62 105.88 0 bottom
CG7019  0.47U_0201_4V_M  [C_0201]  34.95 105.88 0 bottom
CG7020  0.47U_0201_4V_M  [C_0201]  36.35 105.88 0 bottom
CG7021  0.47U_0201_4V_M  [C_0201]  37.74 105.88 0 bottom
CG7022  0.47U_0201_4V_M  [C_0201]  39.14 105.88 0 bottom
CG7023  0.47U_0201_4V_M  [C_0201]  40.47 105.88 0 bottom
CG7024  0.47U_0201_4V_M  [C_0201]  41.74 105.88 0 bottom
CG7025  0.47U_0201_4V_M  [C_0201]  43.14 105.88 0 bottom
CG7026  0.47U_0201_4V_M  [C_0201]  44.48 105.88 0 bottom
CG7027  0.47U_0201_4V_M  [C_0201]  45.87 105.88 0 bottom
CG7028  0.47U_0201_4V_M  [C_0201]  47.21 105.88 0 bottom
CG7029  0.47U_0201_4V_M  [C_0201]  48.54 105.88 0 bottom
CG7030  0.47U_0201_4V_M  [C_0201]  49.94 105.88 0 bottom
CG7031  0.47U_0201_4V_M  [C_0201]  32.22 103.98 0 bottom
CG7032  0.47U_0201_4V_M  [C_0201]  33.62 103.98 0 bottom
CG7033  0.47U_0201_4V_M  [C_0201]  34.95 103.98 0 bottom
CG7034  0.47U_0201_4V_M  [C_0201]  36.35 103.98 0 bottom
CG7035  0.47U_0201_4V_M  [C_0201]  37.74 103.98 0 bottom
CG7036  0.47U_0201_4V_M  [C_0201]  39.14 103.98 0 bottom
CG7037  0.47U_0201_4V_M  [C_0201]  40.47 103.98 0 bottom
CG7038  0.47U_0201_4V_M  [C_0201]  41.74 103.98 0 bottom
CG7039  0.47U_0201_4V_M  [C_0201]  43.14 103.98 0 bottom
CG7040  0.47U_0201_4V_M  [C_0201]  44.48 103.98 0 bottom
CG7041  0.47U_0201_4V_M  [C_0201]  45.87 103.98 0 bottom
CG7042  0.47U_0201_4V_M  [C_0201]  47.21 103.98 0 bottom
CG7043  0.47U_0201_4V_M  [C_0201]  48.54 103.98 0 bottom
CG7044  0.47U_0201_4V_M  [C_0201]  49.94 103.98 0 bottom
CG7045  0.47U_0201_4V_M  [C_0201]  41.74 110.33 0 bottom
CG7046  0.47U_0201_4V_M  [C_0201]  32.22 103.34 0 bottom
CG7047  0.47U_0201_4V_M  [C_0201]  33.62 103.34 0 bottom
CG7048  0.47U_0201_4V_M  [C_0201]  34.95 103.34 0 bottom
CG7049  0.47U_0201_4V_M  [C_0201]  36.35 103.34 0 bottom
CG7050  0.47U_0201_4V_M  [C_0201]  37.74 103.34 0 bottom
CG7051  0.47U_0201_4V_M  [C_0201]  39.14 103.34 0 bottom
CG7052  0.47U_0201_4V_M  [C_0201]  40.47 103.34 0 bottom
CG7053  0.47U_0201_4V_M  [C_0201]  41.74 103.34 0 bottom
CG7054  0.47U_0201_4V_M  [C_0201]  43.14 103.34 0 bottom
CG7055  0.47U_0201_4V_M  [C_0201]  44.48 103.34 0 bottom
CG7056  0.47U_0201_4V_M  [C_0201]  45.87 103.34 0 bottom
CG7057  0.47U_0201_4V_M  [C_0201]  47.21 103.34 0 bottom
CG7058  0.47U_0201_4V_M  [C_0201]  48.54 103.34 0 bottom
CG7059  0.47U_0201_4V_M  [C_0201]  49.94 103.34 0 bottom
CG7060  0.47U_0201_4V_M  [C_0201]  40.47 110.33 0 bottom
CG7061  0.47U_0201_4V_M  [C_0201]  32.22 102.71 0 bottom
CG7062  0.47U_0201_4V_M  [C_0201]  33.62 102.71 0 bottom
CG7063  0.47U_0201_4V_M  [C_0201]  34.95 102.71 0 bottom
CG7064  0.47U_0201_4V_M  [C_0201]  36.35 102.71 0 bottom
CG7065  0.47U_0201_4V_M  [C_0201]  37.74 102.71 0 bottom
CG7066  0.47U_0201_4V_M  [C_0201]  39.14 102.71 0 bottom
CG7067  0.47U_0201_4V_M  [C_0201]  40.47 102.71 0 bottom
CG7068  0.47U_0201_4V_M  [C_0201]  41.74 102.71 0 bottom
CG7069  0.47U_0201_4V_M  [C_0201]  43.14 102.71 0 bottom
CG7070  0.47U_0201_4V_M  [C_0201]  44.48 102.71 0 bottom
CG7071  0.47U_0201_4V_M  [C_0201]  45.87 102.71 0 bottom
CG7072  0.47U_0201_4V_M  [C_0201]  47.21 102.71 0 bottom
CG7073  0.47U_0201_4V_M  [C_0201]  48.54 102.71 0 bottom
CG7074  0.47U_0201_4V_M  [C_0201]  49.94 102.71 0 bottom
CG7075  0.47U_0201_4V_M  [C_0201]  41.74 102.07 0 bottom
CG7076  0.47U_0201_4V_M  [C_0201]  43.14 102.07 0 bottom
CG7077  0.47U_0201_4V_M  [C_0201]  44.48 102.07 0 bottom
CG7078  0.47U_0201_4V_M  [C_0201]  45.87 109.06 0 bottom
CG7079  0.47U_0201_4V_M  [C_0201]  47.21 109.06 0 bottom
CG7080  0.47U_0201_4V_M  [C_0201]  48.54 109.06 0 bottom
CG7081  0.47U_0201_4V_M  [C_0201]  49.94 109.06 0 bottom
CG7082  0.47U_0201_4V_M  [C_0201]  15.15 76.61 180 bottom
CG7083  0.47U_0201_4V_M  [C_0201]  2.6 75.87 0 bottom
CG7084  22U_0603_4V_M  [C_0603]  51.5 125.69 0 bottom
CG7085  0.1U_0201_6.3V6K  [C_0201]  72.96 60.9 270 bottom
CG7087  0.1U_0201_6.3V6K  [C_0201]  74.52 91.66 180 bottom
CG7088  0.1U_0201_6.3V6K  [C_0201]  73.34 89.84 90 bottom
CG7089  2200P_0402_25V7K  [C_0402]  71.77 91.34 180 bottom
CG7090  2200P_0402_25V7K  [C_0402]  76.15 62.19 180 bottom
CG7091  0.1U_0201_6.3V6K  [C_0201]  4 3.75 0 top
CG7092  0.1U_0201_6.3V6K  [C_0201]  66.87 89.72 90 bottom
CG7093  0.1U_0201_6.3V6K  [C_0201]  77.22 62.38 270 bottom
CG7094  2200P_0402_25V7K  [C_0402]  3.76 8.46 90 top
CG7095  2200P_0402_25V7K  [C_0402]  70.74 64.67 270 bottom
CG7096  0.1U_0402_10V7K  [C_0402]  66.36 92.56 270 bottom
CG7097  220P_0402_50V8J  [C_0402]  66.87 97.23 90 bottom
CG7098  10U_0603_6.3V6M  [C_0603]  65.77 97.42 90 bottom
CG7099  220P_0402_50V8J  [C_0402]  67.94 97.23 90 bottom
CG7100  10U_0603_6.3V6M  [C_0603]  63.44 92.74 270 bottom
CG7101  10U_0402_6.3V6M  [C_0402]  64.52 92.56 270 bottom
CG7103  0.1U_0402_16V7K  [C_0402]  67.31 92.56 270 bottom
CG7104  22U_0603_4V_M  [C_0603]  68.31 92.22 0 bottom
CG7105  0.1U_0201_6.3V6K  [C_0201]  72.49 92.55 180 bottom
CG7106  0.1U_0201_6.3V6K  [C_0201]  4.01 3.16 0 top
CG7107  0.22U_0402_10V6K  [C_0402]  3.28 3.89 180 top
CG7108  1U_0201_4V6M  [C_0201]  53.59 95.62 90 bottom
CG7109  4.7U_0402_4V_M  [C_0402]  56.26 97.64 270 bottom
CG7110  22U_0603_4V_M  [C_0603]  57.34 97.94 270 bottom
CG7115  1000P_0402_50V  [C_0402]  2.62 28.16 180 top
CG7116  1000P_0402_50V  [C_0402]  2.62 32.29 180 top
CG7117  2.2U_0402_6.3V6M  [C_0402]  70.74 96.03 90 top
CG7118  47P_0402_50V_5%  [C_0402]  11.62 31.7 90 top
CG7119  47P_0402_50V_5%  [C_0402]  11.62 30.88 270 top
CG7120  0.015U_0402_25V  [C_0402]  3.81 39.39 90 top
CG7121  0.015U_0402_25V  [C_0402]  2.62 31.4 180 top
CG7122  1000P_0402_50V  [C_0402]  11.63 38.09 0 top
CG7123  1000P_0402_50V  [C_0402]  11.56 35.13 90 top
CG7124  1000P_0402_50V  [C_0402]  12.51 33.42 90 top
CG7125  4.7U_0402_4V_M  [C_0402]  63.8 98.58 0 bottom
CG7126  0.47U_0201_4V_M  [C_0201]  61.72 113.53 90 bottom
CG7127  0.47U_0201_4V_M  [C_0201]  61.09 113.53 90 bottom
CG7133  0.47U_0201_4V_M  [C_0201]  60.45 113.53 90 bottom
CG7134  0.47U_0201_4V_M  [C_0201]  59.18 113.53 90 bottom
CG7135  1U_0201_4V6M  [C_0201]  52.55 97.69 180 bottom
CG7136  4.7U_0402_4V_M  [C_0402]  63.8 99.53 0 bottom
CG7137  0.47U_0201_4V_M  [C_0201]  57.91 113.53 90 bottom
CG7138  0.47U_0201_4V_M  [C_0201]  57.28 113.53 90 bottom
CG7139  1U_0201_4V6M  [C_0201]  52.55 98.26 180 bottom
CG7140  0.47U_0201_4V_M  [C_0201]  62.99 113.53 90 bottom
CG7141  0.1U_0402_10V7K  [C_0402]  65.34 73.38 270 top
CG7142  0.1U_0402_10V7K  [C_0402]  61.98 75.03 270 top
CG7143  0.47U_0201_4V_M  [C_0201]  65.49 83.15 0 top
CG7144  0.47U_0201_4V_M  [C_0201]  65.49 81.88 0 top
CG7145  0.47U_0201_4V_M  [C_0201]  63.67 84.42 180 top
CG7146  0.47U_0201_4V_M  [C_0201]  65.49 85.05 0 top
CG7147  0.47U_0201_4V_M  [C_0201]  63.67 83.15 180 top
CG7148  0.47U_0201_4V_M  [C_0201]  63.67 81.88 180 top
CG7149  0.47U_0201_4V_M  [C_0201]  63.67 81.24 180 top
CG7150  0.47U_0201_4V_M  [C_0201]  65.49 80.61 0 top
CG7151  0.47U_0201_4V_M  [C_0201]  63.67 79.97 180 top
CG7152  0.47U_0201_4V_M  [C_0201]  63.67 78.07 180 top
CG7153  0.47U_0201_4V_M  [C_0201]  65.49 78.7 0 top
CG7157  0.47U_0201_4V_M  [C_0201]  65.49 79.34 0 top
CG7159  2200P_0402_25V7K  [C_0402]  2.84 9.4 90 top
CG7160  1U_0402_6.3V6K  [C_0402]  8.53 38.57 180 top
CH36  4.7U_0402_6.3V6M  [C_0402]  95.41 22.35 270 top
CH45  8.2P_0402_50V8B  [C_0402]  116.72 30.92 0 bottom
CH46  8.2P_0402_50V8B  [C_0402]  115.86 30.92 180 bottom
CH47  12P_0402_50V8J  [C_0402]  88.95 50.13 90 bottom
CH48  12P_0402_50V8J  [C_0402]  88.95 47.59 270 bottom
CH49  0.1U_0402_16V7K  [C_0402]  118.24 29.57 270 bottom
CH52  1U_0603_10V6K~D  [C_0603]  121.22 24.98 90 top
CH53  1U_0603_10V6K~D  [C_0603]  119.97 24.98 90 top
CH80  1U_0402_6.3V6K~D  [C_0402]  119.13 28.65 90 bottom
CH82  1U_0402_6.3V6K~D  [C_0402]  117.13 47.14 90 bottom
CH102  10U_0603_6.3V6M~D  [C_0603]  101.12 96.37 270 bottom
CH103  10U_0603_6.3V6M~D  [C_0603]  101.35 98.64 0 bottom
CH104  10U_0603_6.3V6M~D  [C_0603]  101.35 99.85 0 bottom
CH105  1U_0201_6.3V6M  [C_0201]  97.18 108.23 0 bottom
CH106  1U_0201_6.3V6M  [C_0201]  99.25 105.86 270 bottom
CH107  1U_0201_6.3V6M  [C_0201]  101.19 104.41 180 bottom
CH118  10U_0402_6.3V6M  [C_0402]  124.95 90.79 90 bottom
CH119  10U_0402_6.3V6M  [C_0402]  118.35 91.23 90 bottom
CH120  10U_0402_6.3V6M  [C_0402]  100.03 87.34 180 bottom
CH121  10U_0402_6.3V6M  [C_0402]  99.14 86.2 180 bottom
CH122  10U_0402_6.3V6M  [C_0402]  116.68 91.04 90 bottom
CH123  10U_0402_6.3V6M  [C_0402]  112.97 86.34 270 bottom
CH124  10U_0402_6.3V6M  [C_0402]  125.91 88.18 90 bottom
CH125  10U_0402_6.3V6M  [C_0402]  119.44 91.2 90 bottom
CH126  10U_0402_6.3V6M  [C_0402]  102.62 90.48 180 bottom
CH127  10U_0402_6.3V6M  [C_0402]  99.76 88.28 90 bottom
CH128  10U_0402_6.3V6M  [C_0402]  125.73 86.27 270 bottom
CH129  22U_0603_6.3V6M  [C_0603]  110.74 86.83 270 bottom
CH130  22U_0603_6.3V6M  [C_0603]  115.13 86.77 270 bottom
CH131  22U_0603_6.3V6M  [C_0603]  128.33 86.9 270 bottom
CH132  22U_0603_6.3V6M  [C_0603]  136.08 86.9 270 bottom
CH173  0.1U_0402_10V7K  [C_0402]  120.02 28.65 90 bottom
CH174  0.1U_0402_10V  [C_0402]  117.6 26.81 90 bottom
CH175  0.1U_0402_10V  [C_0402]  89.48 29.15 180 top
CH176  1U_0402_6.3V6K~D  [C_0402]  98.71 27.94 270 bottom
CH180  1U_0402_6.3V6K~D  [C_0402]  104.39 40.21 90 bottom
CH181  22U_0805_6.3V6M~D  [C_0805]  105.77 40.6 0 bottom
CH182  1U_0603_10V6K  [C_0603]  96.02 27.62 270 bottom
CH186  0.1U_0402_10V7K  [C_0402]  109.03 35.82 180 bottom
CH187  1U_0402_6.3V6K~D  [C_0402]  92.21 51.31 90 top
CH188  1U_0402_6.3V6K~D  [C_0402]  107.86 34.93 180 bottom
CH190  0.1U_0402_10V7K  [C_0402]  109.61 34.93 180 bottom
CH192  0.1U_0402_10V7K  [C_0402]  112.37 38.93 270 bottom
CH193  0.1U_0402_16V7K~D  [C_0402]  97.46 90.32 0 bottom
CH194  0.1U_0402_16V7K~D  [C_0402]  139.31 108.04 0 top
CH195  0.1U_0402_16V7K~D  [C_0402]  140.08 112.79 90 top
CH197  0.1U_0402_10V7K  [C_0402]  139.2 48.92 180 top
CH201  0.1U_0201_6.3V6K  [C_0201]  12.7 16.18 90 bottom
CH202  0.22U_0201_6.3V  [C_0201]  107.76 51.5 270 top
CH203  0.22U_0201_6.3V  [C_0201]  107.19 51.5 270 top
CH204  0.22U_0201_6.3V  [C_0201]  108.94 51.46 270 top
CH205  0.22U_0201_6.3V  [C_0201]  108.36 51.46 270 top
CH206  0.22U_0201_6.3V  [C_0201]  109.63 50.24 90 top
CH207  0.22U_0201_6.3V  [C_0201]  110.21 50.24 90 top
CH208  0.22U_0201_6.3V  [C_0201]  110.81 50.6 90 top
CH209  0.22U_0201_6.3V  [C_0201]  111.38 50.6 90 top
CH210  0.22U_0201_6.3V  [C_0201]  120.31 45.49 180 top
CH211  0.22U_0201_6.3V  [C_0201]  120.31 46.07 180 top
CH212  0.22U_0201_6.3V  [C_0201]  119.31 41.85 180 top
CH213  0.22U_0201_6.3V  [C_0201]  119.31 42.48 180 top
CH214  0.22U_0201_6.3V  [C_0201]  118.74 44.25 0 top
CH215  0.22U_0201_6.3V  [C_0201]  118.74 44.82 0 top
CH216  0.22U_0201_6.3V  [C_0201]  118.74 43.68 0 top
CH217  0.22U_0201_6.3V  [C_0201]  118.74 43.1 0 top
CH218  0.22U_0201_6.3V  [C_0201]  114.21 51.91 270 top
CH219  0.22U_0201_6.3V  [C_0201]  114.78 51.91 270 top
CH220  0.22U_0201_6.3V  [C_0201]  113.57 51.91 270 top
CH221  0.22U_0201_6.3V  [C_0201]  113 51.91 270 top
CH222  0.22U_0201_6.3V  [C_0201]  115.92 51.91 270 top
CH223  0.22U_0201_6.3V  [C_0201]  115.35 51.91 270 top
CH224  0.22U_0201_6.3V  [C_0201]  116.56 51.91 270 top
CH225  0.22U_0201_6.3V  [C_0201]  117.16 51.88 270 top
CH226  0.1U_0402_10V7K  [C_0402]  120.02 24.04 270 top
CH231  10P_0402_50V8J  [C_0402]  124.08 21.36 0 top
CH233  4.7U_0603_6.3V6M  [C_0603]  99.09 29.52 0 bottom
CH242  10P_0402_50V8J  [C_0402]  88.01 140.06 0 bottom
CH244  10P_0402_50V8J  [C_0402]  123.81 17.74 0 top
CH245  10P_0402_50V8J  [C_0402]  96.33 20.55 270 top
CH246  10P_0402_50V8J  [C_0402]  111.38 23.22 270 bottom
CH247  10P_0402_50V8J  [C_0402]  64.72 119.28 180 top
CH248  10P_0402_50V8J  [C_0402]  105.14 23.84 0 bottom
CH249  10P_0402_50V8J  [C_0402]  104.28 23.84 180 bottom
CH250  10P_0402_50V8J  [C_0402]  105.35 17.44 270 top
CH251  10P_0402_50V8J  [C_0402]  108.97 15.27 90 top
CH252  10P_0402_50V8J  [C_0402]  101.93 22.32 180 bottom
CH253  10P_0402_50V8J  [C_0402]  101.93 23.27 180 bottom
CI38  0.1U_0402_10V6K  [C_0402]  40.64 145.81 90 top
CI39  0.1U_0402_10V6K  [C_0402]  39.62 145.81 90 top
CLIP1  -  [CLIP_10P2X7P2_SHIELDING_CASE1]  67.61 150.13 0 bottom
CLRP1  SHORT PADS  [SHORTPADS]  121.73 23.65 0 top
CM9  0.1U_0402_10V7K  [C_0402]  72.31 143.16 0 top
CM16  0.1U_0402_10V7K  [C_0402]  87.01 25.6 270 bottom
CM17  0.1U_0402_10V7K  [C_0402]  86.09 25.53 270 bottom
CM18  0.1U_0402_10V7K  [C_0402]  93.2 25.53 270 bottom
CM19  22U_0603_6.3V6M  [C_0603]  65.66 131.73 270 top
CM20  0.1U_0402_10V7K  [C_0402]  66.74 131.42 270 top
CM21  1U_0402_6.3V  [C_0402]  88.76 25.58 270 bottom
CM23  0.1U_0402_10V7K  [C_0402]  54.15 142.01 0 top
CM29  10U_0603_6.3V6M  [C_0603]  64.45 131.73 270 top
CM30  1U_0402_6.3V  [C_0402]  92.19 35.29 90 bottom
CM31  10U_0603_6.3V6M  [C_0603]  73.2 132.19 10 top
CM32  0.1U_0402_10V7K  [C_0402]  63.69 140.79 90 top
CM33  1U_0402_6.3V  [C_0402]  89.65 35.29 90 bottom
CM34  0.1U_0402_10V7K  [C_0402]  72.31 140.49 0 top
CM35  0.1U_0402_10V7K  [C_0402]  72.31 141.38 0 top
CM36  0.1U_0402_10V7K  [C_0402]  72.31 142.27 0 top
CM62  0.22U_0201_6.3V  [C_0201]  72.96 138.44 180 top
CM63  0.22U_0201_6.3V  [C_0201]  72.96 139.08 180 top
CM64  0.22U_0201_6.3V  [C_0201]  72.96 135.2 180 top
CM65  0.22U_0201_6.3V  [C_0201]  72.96 135.84 180 top
CM66  0.22U_0201_6.3V  [C_0201]  72.96 139.71 180 top
CM67  0.22U_0201_6.3V  [C_0201]  72.96 136.54 180 top
CM68  0.22U_0201_6.3V  [C_0201]  72.96 137.81 180 top
CM69  0.22U_0201_6.3V  [C_0201]  72.96 137.17 180 top
CM70  0.1U_0402_10V7K  [C_0402]  53.16 142.01 180 top
CM98  0.01U_0402_16V7K  [C_0402]  89.65 24.62 90 bottom
CM99  0.01U_0402_16V7K  [C_0402]  92.31 24.62 90 bottom
CT2  0.22U_0201_6.3V  [C_0201]  78.01 129.62 90 bottom
CT6  0.1U_0201_6.3V6K  [C_0201]  82.47 135.15 90 bottom
CT7  0.1U_0201_6.3V6K  [C_0201]  83.04 135.15 90 bottom
CT8  0.1U_0201_6.3V6K  [C_0201]  81.33 135.15 90 bottom
CT9  0.1U_0201_6.3V6K  [C_0201]  81.9 135.15 90 bottom
CT10  0.1U_0201_6.3V6K  [C_0201]  80.19 135.15 90 bottom
CT11  0.1U_0201_6.3V6K  [C_0201]  79.04 135.15 90 bottom
CT12  0.22U_0201_6.3V  [C_0201]  77.44 129.62 90 bottom
CT14  0.22U_0201_6.3V  [C_0201]  79.52 129.79 90 bottom
CT16  0.22U_0201_6.3V  [C_0201]  78.95 129.79 90 bottom
CT23  0.1U_0201_6.3V6K  [C_0201]  80.76 135.15 90 bottom
CT24  0.1U_0201_6.3V6K  [C_0201]  79.61 135.15 90 bottom
CT25  0.1U_0201_6.3V6K  [C_0201]  76.06 132.19 90 top
CT26  0.1U_0201_6.3V6K  [C_0201]  76.69 132.19 90 top
CT27  0.1U_0201_6.3V6K  [C_0201]  77.9 135.15 90 bottom
CT28  0.1U_0201_6.3V6K  [C_0201]  78.47 135.15 90 bottom
CT29  0.1U_0201_6.3V6K  [C_0201]  76.76 135.15 90 bottom
CT30  0.1U_0201_6.3V6K  [C_0201]  77.33 135.15 90 bottom
CT31  0.1U_0201_6.3V6K  [C_0201]  75.61 135.15 90 bottom
CT32  0.1U_0201_6.3V6K  [C_0201]  76.19 135.15 90 bottom
CT33  0.1U_0201_6.3V6K  [C_0201]  74.47 135.15 90 bottom
CT34  0.1U_0201_6.3V6K  [C_0201]  75.04 135.15 90 bottom
CT35  0.1U_0201_6.3V6K  [C_0201]  74.79 133.39 90 top
CT36  0.1U_0201_6.3V6K  [C_0201]  74.15 133.39 90 top
CT37  27P_0201_25V  [C_0201]  68.5 146.33 270 bottom
CT38  27P_0201_25V  [C_0201]  68.5 147.14 90 bottom
CT39  0.22U_0201_6.3V  [C_0201]  79.98 150.33 180 bottom
CT40  0.22U_0201_6.3V  [C_0201]  79.98 150.9 180 bottom
CT41  0.22U_0201_6.3V  [C_0201]  76.14 149.8 270 bottom
CT42  0.22U_0201_6.3V  [C_0201]  76.71 149.8 270 bottom
CT43  0.1U_0201_6.3V6K  [C_0201]  77.84 137.39 90 top
CT44  0.1U_0201_6.3V6K  [C_0201]  78.47 137.39 90 top
CT45  0.1U_0201_6.3V6K  [C_0201]  64.68 117.57 180 top
CT46  0.1U_0201_6.3V6K  [C_0201]  84.77 141.21 90 top
CT47  1U_0201_6.3V6M  [C_0201]  82.04 145.85 90 top
CT48  1U_0201_6.3V6M  [C_0201]  83.72 144.81 0 top
CT49  1U_0201_6.3V6M  [C_0201]  88.43 145.76 180 bottom
CT50  10U_0402_6.3V6M  [C_0402]  80.58 144.99 90 top
CT51  10U_0402_6.3V6M  [C_0402]  88.01 139.17 0 bottom
CT52  10U_0402_6.3V6M  [C_0402]  88.01 140.95 0 bottom
CT53  10U_0402_6.3V6M  [C_0402]  88.01 141.84 0 bottom
CT54  1U_0201_6.3V6M  [C_0201]  78.97 139.92 180 top
CT55  1U_0201_6.3V6M  [C_0201]  77.47 142.56 270 top
CT56  1U_0201_6.3V6M  [C_0201]  77.06 140.36 180 top
CT57  1U_0201_6.3V6M  [C_0201]  88.54 141.05 180 top
CT58  1U_0201_6.3V6M  [C_0201]  88.54 141.69 180 top
CT59  1U_0201_6.3V6M  [C_0201]  79.44 143.06 90 top
CT60  1U_0201_6.3V6M  [C_0201]  80.23 142.65 0 top
CT61  1U_0201_6.3V6M  [C_0201]  80.23 142.08 0 top
CT62  1U_0201_6.3V6M  [C_0201]  78.97 140.49 180 top
CT63  1U_0201_6.3V6M  [C_0201]  80.64 147.63 90 top
CT64  1U_0201_6.3V6M  [C_0201]  81.43 147.03 0 top
CT65  1U_0201_6.3V6M  [C_0201]  75.56 147.39 270 top
CT66  1U_0201_6.3V6M  [C_0201]  81.22 147.63 90 top
CT67  1U_0201_6.3V6M  [C_0201]  80.07 147.63 90 top
CT68  1U_0201_6.3V6M  [C_0201]  79.5 147.63 90 top
CT69  1U_0201_6.3V6M  [C_0201]  78.93 147.63 90 top
CT70  1U_0201_6.3V6M  [C_0201]  78.04 142.56 270 top
CT71  1U_0201_6.3V6M  [C_0201]  76.1 142.13 180 top
CT72  1U_0201_6.3V6M  [C_0201]  76.1 141.49 180 top
CT73  47U_0603_6.3V6M  [C_0603]  73.85 145.7 270 top
CT74  47U_0603_6.3V6M  [C_0603]  77.03 148.81 90 top
CT75  47U_0603_6.3V6M  [C_0603]  75.82 148.81 90 top
CT77  1U_0201_6.3V6M  [C_0201]  77.11 139.79 0 top
CT78  1U_0201_6.3V6M  [C_0201]  80.64 140.72 270 top
CT79  1U_0201_6.3V6M  [C_0201]  81.28 140.72 270 top
CT80  1U_0201_6.3V6M  [C_0201]  81.9 140.71 270 top
CT81  10U_0402_6.3V6M  [C_0402]  77.23 146.97 180 top
CT82  10U_0402_6.3V6M  [C_0402]  77.23 146.08 180 top
CT83  1U_0201_6.3V6M  [C_0201]  79.18 144.71 90 top
CT84  1U_0201_6.3V6M  [C_0201]  77.06 145.32 180 top
CT85  1U_0201_6.3V6M  [C_0201]  77.94 143.92 0 top
CT86  1U_0201_6.3V6M  [C_0201]  77.13 143.92 180 top
CT88  0.1U_0402_10V6K  [C_0402]  90.12 145.11 180 bottom
CT90  22U_0603_6.3V6M  [C_0603]  104.01 138.39 90 bottom
CT91  22U_0603_6.3V6M  [C_0603]  105.22 138.39 90 bottom
CT92  22U_0603_6.3V6M  [C_0603]  106.43 138.39 90 bottom
CT93  22U_0603_6.3V6M  [C_0603]  107.63 138.39 90 bottom
CT94  0.47U_0402_25V6K  [C_0402]  101.56 147.14 180 top
CT95  0.47U_0402_25V6K  [C_0402]  92.11 146.32 0 top
CT96  0.47U_0402_25V6K  [C_0402]  100.65 146.19 0 top
CT97  0.47U_0402_25V6K  [C_0402]  93.03 147.23 180 top
CT98  2.2U_0402_16V6K  [C_0402]  92.09 139.92 180 bottom
CT99  4.7U_0603_10V6K  [C_0603]  94.55 136.95 180 bottom
CT100  4.7U_0603_10V6K  [C_0603]  91.44 144.24 90 bottom
CT101  10U_0402_6.3V6M  [C_0402]  90.12 144.22 180 bottom
CT102  1U_0201_6.3V6M  [C_0201]  90.39 142.92 0 bottom
CT103  10U_0402_6.3V6M  [C_0402]  92.15 142.08 180 bottom
CT104  0.22U_0402_10V6K  [C_0402]  100.41 142.97 90 top
CT106  1U_0603_25V6K  [C_0603]  101.54 144.05 90 bottom
CT108  0.22U_0201_6.3V  [C_0201]  77.57 131.39 90 bottom
CT109  0.22U_0201_6.3V  [C_0201]  77 131.39 90 bottom
CT110  0.22U_0201_6.3V  [C_0201]  76.3 129.62 90 bottom
CT111  0.22U_0201_6.3V  [C_0201]  76.87 129.62 90 bottom
CT112  220P_0201_25V7K  [C_0201]  98.01 144.96 90 bottom
CT113  220P_0201_25V7K  [C_0201]  98.56 144.96 90 bottom
CT114  100P_0402_50V8J~D  [C_0402]  94.14 16.54 270 bottom
CT115  0.047U_0402_25V7K  [C_0402]  98.4 16.76 90 bottom
CT116  10U_0603_6.3V6M~D  [C_0603]  94.33 18.36 180 bottom
CT117  2200P_0402_25V7K  [C_0402]  95.84 21.54 0 bottom
CT118  0.1U_0402_10V6K  [C_0402]  95.84 19.51 0 bottom
CT121  0.1U_0402_16V7K  [C_0402]  79.01 149.63 180 top
CT122  4.7U_0805_10V4Z  [C_0805]  61.11 142.03 0 bottom
CT123  0.1U_0402_16V7K  [C_0402]  79.07 151.54 180 top
CT124  22U_0603_6.3V6M  [C_0603]  90.79 143.94 270 top
CT153  1U_0201_6.3V6M  [C_0201]  78.97 141.06 180 top
CT154  47U_0603_6.3V6M  [C_0603]  85.79 143.41 0 top
CT155  47U_0603_6.3V6M  [C_0603]  85.79 144.62 0 top
CT157  4.7U_0603_10V6K  [C_0603]  102.81 138.39 90 bottom
CT5361  0.1U_0402_10V6K  [C_0402]  61.23 143.36 0 bottom
CU26  0.1U_0402_16V7K  [C_0402]  87.9 12.16 180 bottom
CU27  2.2U_0603_6.3V6K  [C_0603]  88.14 6.57 180 bottom
CU28  0.1U_0402_16V7K  [C_0402]  85.2 12.16 0 bottom
CU29  0.1U_0402_16V7K  [C_0402]  83.57 8.74 270 bottom
CV1  0.1U_0201_6.3V6K  [C_0201]  62.74 144.21 270 top
CV2  0.1U_0201_6.3V6K  [C_0201]  63.37 144.21 270 top
CV3  0.1U_0201_6.3V6K  [C_0201]  61.59 144.21 270 top
CV4  0.1U_0201_6.3V6K  [C_0201]  60.96 144.21 270 top
CV6  0.1U_0201_6.3V6K  [C_0201]  62.48 142.43 270 top
CV7  0.1U_0201_6.3V6K  [C_0201]  60.07 142.43 270 top
CV8  0.1U_0201_6.3V6K  [C_0201]  61.85 142.43 270 top
CV11  0.1U_0201_6.3V6K  [C_0201]  60.71 142.43 270 top
CV12  0.1U_0201_6.3V6K  [C_0201]  59.82 144.21 270 top
CV13  0.1U_0201_6.3V6K  [C_0201]  59.18 144.21 270 top
CV14  0.1U_0603_25V7K  [C_0603]  40.45 141.25 0 top
CV15  0.47U_0402_50V7K  [C_0402]  30.4 145 90 top
CV17  0.1U_0402_10V7K  [C_0402]  20.56 135.42 270 top
CV18  10U_0603_6.3V6M  [C_0603]  21.7 135.66 270 top
CV20  0.1U_0402_16V7K  [C_0402]  124.02 138.66 270 top
CV23  0.1U_0201_6.3V6K  [C_0201]  110.45 143.72 180 bottom
CV24  0.1U_0201_6.3V6K  [C_0201]  108.67 138.58 0 bottom
CV25  0.1U_0201_6.3V6K  [C_0201]  108.67 139.22 0 bottom
CV26  0.1U_0201_6.3V6K  [C_0201]  112.8 142.95 90 top
CV27  0.1U_0201_6.3V6K  [C_0201]  113.37 142.95 90 top
CV28  0.1U_0201_6.3V6K  [C_0201]  114.62 142.19 90 top
CV29  0.1U_0201_6.3V6K  [C_0201]  110.13 141.81 90 top
CV30  0.1U_0201_6.3V6K  [C_0201]  115.19 142.19 90 top
CV31  0.1U_0201_6.3V6K  [C_0201]  110.71 141.81 90 top
CV32  0.1U_0201_6.3V6K  [C_0201]  116.42 142.95 90 top
CV33  0.1U_0201_6.3V6K  [C_0201]  116.99 142.95 90 top
CV34  10U_0402_6.3V6M  [C_0402]  107.38 143.93 270 top
CV35  0.1U_0201_6.3V6K  [C_0201]  107.89 145.98 90 top
CV375  10P_0402_50V8J  [C_0402]  27.7 141.7 180 top
CV1056  0.1U_0402_16V7K  [C_0402]  124.97 138.66 270 top
CV1057  0.1U_0201_6.3V6K  [C_0201]  138.94 138.81 270 bottom
CV1058  0.1U_0201_6.3V6K  [C_0201]  138.3 138.81 270 bottom
CV1059  0.1U_0201_6.3V6K  [C_0201]  133.6 138.88 270 bottom
CV1060  0.1U_0201_6.3V6K  [C_0201]  134.18 138.88 270 bottom
CV1061  0.1U_0201_6.3V6K  [C_0201]  124.08 138.75 270 bottom
CV1062  0.1U_0201_6.3V6K  [C_0201]  124.71 138.75 270 bottom
CV1063  0.1U_0201_6.3V6K  [C_0201]  128.84 138.81 270 bottom
CV1064  0.1U_0201_6.3V6K  [C_0201]  129.48 138.81 270 bottom
